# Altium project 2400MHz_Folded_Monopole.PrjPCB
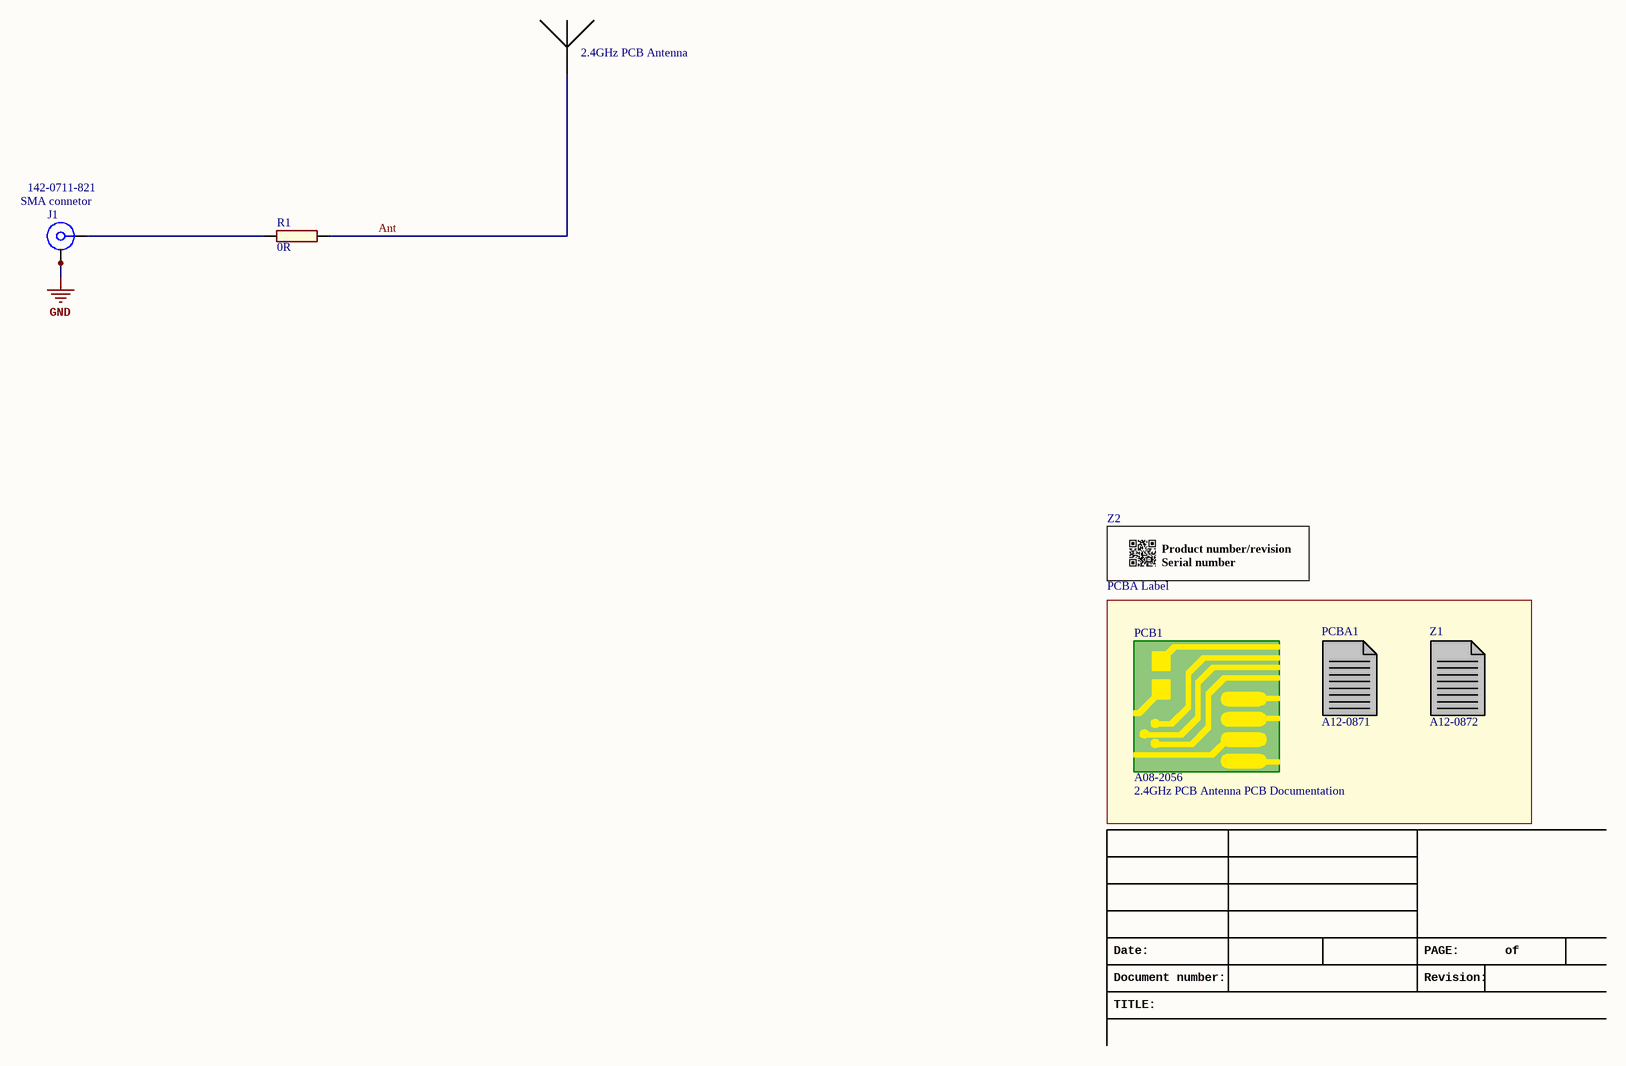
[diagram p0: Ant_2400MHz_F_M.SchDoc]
1 sheet, 6 parts. Net scope: global (net labels, ports and power ports of the same name join across sheets).
Board file: Ant_2400MHz_F_M.PcbDoc

## Sheet Ant_2400MHz_F_M.SchDoc: 2.4 PCB Antenna Schematics
size A3; Organization: ATMEL Norway; Address1: Vestre Rosten 79; Address2: N-7075 TILLER; Address3: NORWAY; DocumentNumber: A09-2257; Revision: 1; SheetNumber: 1; SheetTotal: 1; PageSetup: Record=PageOptions¦CenterHorizontal=True¦CenterVertical=True¦PrintScale=1.01¦XCorrection=1.00¦YCorrection=1.00¦PrintKind=1¦BorderSize=5000000¦LeftOffset=0¦BottomOffset=0¦Orientation=2¦PaperLength=1000¦PaperWidth=1000¦Scale=100¦PaperSource=7¦PrintQuality=-4¦MediaType=1¦DitherType=10¦PaperKind=Letter¦PrintScaleMode=1

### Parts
J1  SMA connetor  value 142-0711-821  [AP8-00443]
PCB1  value 2.4GHz PCB Antenna PCB Documentation  AN: A08-2056  (hidden comment: PCB)  (mechanical)
PCBA1  AN: A12-0871  (hidden comment: PCBADOC)  (mechanical)
R1  value 0R  [AP2-00000]  (hidden comment: Comment)
Z1  AN: A12-0872  (hidden comment: TESTDOC)  (mechanical)
Z2  value PCBA Label  [AP8-00317]  (hidden comment: PCBA_LABEL)

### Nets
GND: J1.2 J1.2.1
Ant: R1.2
NetJ1_1: J1.1 R1.1

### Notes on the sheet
- 2.4GHz PCB Antenna
- Date:
- PAGE:
- of
- TITLE:
- Document number:
- Revision:

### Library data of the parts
J1 = A08-1047: End Launch Jack Receptacle, Round Contact (de21535); Manufacturer: EMERSON; PartGroup: Mechanical devices,Connectors,Coaxial; Art.-Nr.: 21535; ComponentStatus: 'Active (verified)'
PCB1 = A08-2056: 2.4GHz PCB Antenna PCB Documentation; PartGroup: Mechanical devices,Printed circuit boards; TemperatureRange: 0 deg C to +85 deg C; ComponentStatus: 'Active (verified)'
PCBA1 = A12-0871: 2.4GHz PCB Antenna PCBA documentation; PartGroup: Documentation,PCBA Documents,Atmel; ComponentStatus: 'Active (verified)'
R1 = A02-0163: RES 0.0 OHM 1/16W 0402 SMD; PartGroup: Resistors,SMD,0402 1%; Manufacturer: (n/a); MPN: RMCF0402ZT0R00; Tolerance: 1 %; TemperatureRange: -55 - +125 deg C; ComponentStatus: 'Active (verified)'
Z1 = A12-0872: 2.4GHz PCB Antenna Production test instructions; PartGroup: Documentation,Procedures,Test Instructions; ComponentStatus: 'Active (verified)'
Z2 = A09-0611: PCBA identification label PP Top White Gloss; PartGroup: Mechanical devices,Packaging materials,Printed Labels; Manufacturer: ACT Logimark AS; MPN: 505462; ComponentStatus: 'Active (verified)'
